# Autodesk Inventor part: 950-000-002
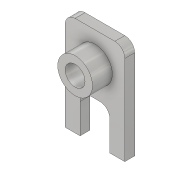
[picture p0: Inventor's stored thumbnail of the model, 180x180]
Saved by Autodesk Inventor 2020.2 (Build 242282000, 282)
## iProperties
Created: 2018-01
Part Number: 950-000-002
Material: Aluminium 6061
Document SubType Name: Modeling
Designer: F.Stasiak
Density: 2.7 g/cm^3
Appearance: Aluminium — polerowane
Manager: www.cadconsulting.pl
Company: Fabian Stasiak CAD Consulting
Author: F.Stasiak
Subject: Zbiór ćwiczeń. Autodesk Inventor 2020. Kurs podstawowy
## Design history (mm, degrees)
sketch "Szkic1"
  geometry: L1 (-30, 50)-(30, 50); L2 (30, 50)-(30, -50); L3 (30, -50)-(-30, -50); L4 (-30, -50)-(-30, 50); L5 (-30, 50)-(30, -50); L6 (30, 50)-(-30, -50); 1 further point
  constraints: 12 end point, 2 midpoint, 2 parallel, 1 horizontal, 1 perpendicular
  dimensions: "d0" = 60 distance of L2.end L3.end; "d1" = 100 distance of L1.end L2.end
extrude "Wyciągnięcie proste1" new body sketch "Szkic1" distance "d2" = 10; taper "d3" = 0 deg
sketch "Szkic2"
  geometry: L1 (-30, -50)-(30, -50) reference; C1 r 17.5 at (0, 20); 1 further point
  constraints: 1 centre point, 1 vertical alignment
  dimensions: "d4" = 35 diameter of C1; "d5" = 70 distance from line of L1 C1.centre
extrude "Wyciągnięcie proste2" join sketch "Szkic2" distance "d6" = 20; taper "d7" = 0 deg
hole "Otwór1" diameter "d10" = 20; stored, may be unused: countersink angle "d14" = 90 deg, drill point angle "d16" = 118 deg; dims "d8" = 10, "d9" = 10, "d11" = 6, "d12" = 4, "d13" = 2, "d15" = 8
sketch "Szkic3"
  geometry: L1 (-30, -50)-(30, -50) reference; L2 (-15, -50)-(15, -50); L3 (15, -50)-(15, -10); L4 (15, -10)-(-15, -10); L5 (-15, -10)-(-15, -50); 2 further points
  constraints: 8 end point, 2 equal length, 2 midpoint, 1 horizontal, 1 perpendicular
  dimensions: "d17" = 30 distance of L4.end L3.end; "d18" = 40 distance of L3.end L2.end
extrude "Wyciągnięcie proste3" cut sketch "Szkic3" extent not by distance; stored distance "d19" = 20; taper "d20" = 0 deg
fillet "Zaokrąglenie1" dims "d21" = 10
node "Bryła1"
